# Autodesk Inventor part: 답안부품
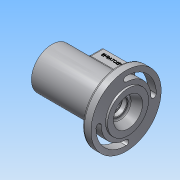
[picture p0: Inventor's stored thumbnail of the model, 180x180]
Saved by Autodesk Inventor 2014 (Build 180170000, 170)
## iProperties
Created: 2017-05
Part Number: 답안부품
Material: 알루미늄 6061
Document SubType Name: Modeling
Designer: NET
Density: 2.71 g/cm^3
Appearance: 알루미늄 - 평지
Mass: 734.189 g
Surface Area: 637.35 cm^2
Volume: 270.918 cm^3
Author: NET
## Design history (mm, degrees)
sketch "스케치1"
  geometry: L1 (-57.5, 31)-(57.5, 31); L2 (57.5, 31)-(57.5, 0); L3 (57.5, 0)-(-57.5, 0); L4 (-57.5, 0)-(-57.5, 31); 2 further points
  constraints: 8 end point, 2 coincident, 2 parallel, 1 horizontal, 1 midpoint, 1 perpendicular
  dimensions: "d0" = 62 diameter of L1.end L3; "d1" = 115 distance of L1.start L1.end
revolve "회전1" sketch "스케치1" stored, may be unused: angle "d2" = 90 deg
node "작업 평면1"
sketch "스케치2"
  geometry: C1 r 53 at (0, 0); 1 further point
  constraints: 1 centre point, 1 coincident
  dimensions: "d4" = 106 diameter of C1
extrude "돌출1" join sketch "스케치2" distance "d5" = 13; taper "d6" = 0 deg
fillet "모깎기1" dims "d7" = 3
sketch "스케치3"
  geometry: L1 (-57.5, -31)-(-57.5, 31) reference; L2 (-57.5, 31)-(41.5, 31) reference; L3 (41.5, 31)-(41.5, 50) reference; L4 (44.5, 53)-(54.5, 53) reference; L5 (54.5, 53)-(54.5, 31) reference; L6 (54.5, 31)-(57.5, 31) reference; L7 (57.5, 31)-(57.5, -31) reference; L8 (57.5, -31)-(54.5, -31) reference; L9 (54.5, -31)-(54.5, -53) reference; L10 (54.5, -53)-(44.5, -53) reference; L11 (41.5, -50)-(41.5, -31) reference; L12 (41.5, -31)-(-57.5, -31) reference; L13 (-57.5, 0)-(57.5, 0); L14 (57.5, 0)-(57.5, 22); L15 (57.5, 22)-(45.318, 16.779); L16 (43.5, 14.022)-(43.5, 12.904); L17 (42.8, 12.5)-(36.5, 12.5); L18 (36.2, 12.2)-(36.2, 10); L19 (36.2, 10)-(33.5, 10); L20 (33.5, 10)-(33.5, 13.5); L21 (30.5, 16.5)-(28.5, 16.5); L22 (28.5, 16.5)-(28.5, 17.2); L23 (28.2, 17.5)-(18.5, 17.5); L24 (17.5, 18.5)-(17.5, 23); L25 (43.5, 12.904)-(42.8, 12.5); L26 (14.5, 26)-(-17.5, 26); L27 (-20.5, 23)-(-20.5, 18.5); L28 (-21.5, 17.5)-(-31.5, 17.5); L29 (-31.5, 17.5)-(-31.5, 18.5); L30 (-31.5, 18.5)-(-33.25, 18.5); L31 (-33.25, 18.5)-(-33.25, 17.5); L32 (-33.25, 17.5)-(-39.5, 17.5); L33 (-39.5, 17.5)-(-39.5, 20); L34 (-39.5, 20)-(-45.5, 20); L35 (-45.5, 20)-(-45.5, 24); L36 (-45.5, 24)-(-48.5, 24); L37 (-48.5, 24)-(-48.5, 0); L38 (-21.5, 17.5)-(-20.5, 18.5); L39 (17.5, 18.5)-(18.5, 17.5); A1 r 3 centre (44.5, 50) between (44.5, 53) and (41.5, 50) reference; A2 r 3 centre (44.5, -50) between (41.5, -50) and (44.5, -53) reference; A3 r 0.3 centre (36.5, 12.2) between (36.5, 12.5) and (36.2, 12.2); A4 r 3 centre (30.5, 13.5) between (33.5, 13.5) and (30.5, 16.5); A5 r 3 centre (46.5, 14.022) between (45.318, 16.779) and (43.5, 14.022); A6 r 3 centre (14.5, 23) between (17.5, 23) and (14.5, 26); A7 r 3 centre (-17.5, 23) between (-17.5, 26) and (-20.5, 23); A8 r 0.3 centre (28.2, 17.2) between (28.5, 17.2) and (28.2, 17.5); 11 further points
  constraints: 54 end point, 18 point on line, 13 perpendicular, 12 point on circle, 12 tangent, 7 parallel, 6 centre point, 3 midpoint, 1 collinear, 1 vertical alignment
  dimensions: "d57" = 24 horizontal distance of L13.end point (33.5, 16.5); "d58" = 5 distance of point (33.5, 16.5) L21.end; "d62" = 44 diameter of L14.end L13; "d64" = 14 distance from line of L14.end L16; "d66" = 32 diameter of point (43.5, 16) L13; "d67" = 30 deg angle of L25 L17; "d68" = 0.7 horizontal distance of L16.end L17.start; "d69" = 7.3 horizontal distance of L16.end point (36.2, 12.5); "d70" = 0.3 radius of A3; "d71" = 25 diameter of L17 L13; "d72" = 20 diameter of L19 L13; "d73" = 33 diameter of L21 L13; "d75" = 3 radius of A4; "d76" = 3 radius of A5; "d77" = 11 distance of point (28.5, 17.5) point (17.5, 17.5); "d78" = 38 distance of point (17.5, 26) point (-20.5, 26); "d79" = 52 diameter of L26 L13; "d80" = 35 diameter of L23 L13; "d81" = 3 radius of A6; "d82" = 3 radius of A7; "d83" = 11 distance of point (-20.5, 17.5) L28.end; "d84" = 1.75 distance of L29.end L30.end; "d85" = 35 diameter of L28 L13; "d86" = 1 distance of L28.start point (-20.5, 17.5); "d87" = 1 distance of L27.end point (-20.5, 17.5) (= d86); "d88" = 1 distance of L24.start point (17.5, 17.5) (= d86); "d89" = 1 distance of L23.end point (17.5, 17.5) (= d88); "d90" = 37 diameter of L30 L13; "d91" = 3 distance of L35.end L36.end; "d92" = 9 horizontal distance of L36.end L33.end; "d93" = 17 horizontal distance of L36.end L29.end; "d94" = 48 diameter of L36 L13; "d95" = 40 diameter of L34 L13; "d96" = 35 diameter of L32 L13; "d97" = 0.3 radius of A8
revolve "회전2" sketch "스케치3" stored, may be unused: angle "d98" = 90 deg
sketch "스케치4"
  geometry: C1 r 31 at (0, 0) reference; 1 further point
  constraints: 1 coincident
hole "구멍1" sketch "스케치4" at (0, 0) diameter "d99" = 40.376; stored, may be unused: countersink angle "d103" = 90 deg, drill point angle "d105" = 0 deg; dims "d100" = 9, "d101" = 4, "d102" = 2, "d104" = 11
sketch "스케치5"
  geometry: C1 r 31 at (0, 0) reference; A1 r 41.5 centre (0, 0) between (41.5, 0) and (0, -41.5); A2 r 4 centre (41.5, 0) between (45.5, 0) and (37.5, 0); A3 r 4 centre (0, -41.5) between (0, -37.5) and (0, -45.5); A4 r 4 centre (0, 41.5) between (0, 37.5) and (0, 45.5); A5 r 4 centre (-41.5, 0) between (-45.5, 0) and (-37.5, 0); A6 r 45.5 centre (0, 0) between (0, 45.5) and (-45.5, 0); A7 r 45.5 centre (0, 0) between (0, -45.5) and (45.5, 0); A8 r 37.5 centre (0, 0) between (0, 37.5) and (-37.5, 0); A9 r 37.5 centre (0, 0) between (0, -37.5) and (37.5, 0)
  constraints: 20 point on circle, 9 centre point, 3 coincident
  dimensions: "d106" = 83 diameter of A1; "d109" = 8 diameter of A2; "d110" = 8 diameter of A3; "d111" = 8 diameter of A4; "d112" = 8 diameter of A5
extrude "돌출2" cut sketch "스케치5" stored distance "d113" = 14; taper "d114" = 0 deg
node "작업 평면2"
sketch "스케치6"
  geometry: L1 (-23.5, -20)-(-23.5, 20); L2 (-23.5, 20)-(26.5, 20); L3 (26.5, 20)-(26.5, -20); L4 (26.5, -20)-(-23.5, -20); L5 (1.5, -20)-(1.5, 20); L6 (-23.5, 0)-(26.5, 0); L7 (57.5, 31)-(57.5, -31) reference; 1 further point
  constraints: 12 end point, 4 midpoint, 2 parallel, 2 perpendicular, 1 horizontal alignment, 1 vertical
  dimensions: "d118" = 56 distance from line of L5.start L7; "d119" = 50 distance from line of L1 L6.end; "d120" = 40 distance between parallel lines of L2 L4
extrude "돌출3" join sketch "스케치6" stored distance "d121" = 14; taper "d122" = 0 deg
sketch "스케치7"
  geometry: L1 (-26.5, 20)-(23.5, 20) reference; L2 (-26.5, -20)-(-26.5, 20) reference; L3 (23.5, -20)-(-26.5, -20) reference; L4 (-1.5, 20)-(-1.5, -20); L5 (-17.5, 11)-(14.5, 11); L6 (14.5, 11)-(14.5, -11); L7 (14.5, -11)-(-17.5, -11); L8 (-17.5, -11)-(-17.5, 11); 4 further points
  constraints: 10 end point, 5 midpoint, 2 parallel, 1 horizontal, 1 horizontal alignment, 1 perpendicular, 1 vertical alignment
  dimensions: "d129" = 32 distance of L5.start L5.end; "d130" = 22 distance of L5.end L6.end
extrude "돌출4" cut sketch "스케치7" stored distance "d125" = 14; taper "d126" = 0 deg
fillet "모깎기2" dims "d127" = 3
fillet "모깎기3" dims "d128" = 3
sketch "스케치8"
  geometry: L1 (-17.5, 11)-(14.5, 11) reference; L2 (14.5, -11)-(-17.5, -11) reference; L3 (-1.5, 11)-(-1.5, -11); L4 (-22, 15.5)-(19, 15.5); L5 (19, 15.5)-(19, -15.5); L6 (19, -15.5)-(-22, -15.5); L7 (-22, -15.5)-(-22, 15.5); 9 further points
  constraints: 10 end point, 6 midpoint, 4 coincident, 2 parallel, 1 horizontal, 1 horizontal alignment, 1 perpendicular, 1 vertical alignment
  dimensions: "d132" = 41 distance of L4.start L4.end; "d133" = 31 distance of L4.end L5.end
hole "구멍2" sketch "스케치8" at (-22, 15.5), (19, 15.5), (-22, -15.5), (19, -15.5) diameter "d134" = 2.459; stored, may be unused: countersink angle "d138" = 90 deg, drill point angle "d140" = 118 deg; dims "d135" = 6, "d136" = 4, "d137" = 2, "d139" = 8
fillet "모깎기4" dims "d141" = 3
chamfer "모따기1" distance "d142" = 1; stored, may be unused: second distance "d143" = 2, angle "d144" = 45 deg
sketch "스케치9"
  geometry: L1 (44, 0)-(0, 0) reference; L2 (-34, -75)-(-34, -13) reference; 2 further points
  constraints: 1 other
  dimensions: "d145" = 56 distance from line of point (22, -8) L2; "d146" = 8 distance from line of L1 point (22, -8)
feature "엠보싱1" sketch "스케치9" dims "d147" = 0.5, "d148" = 0
chamfer "모따기2" distance "d149" = 1; stored, may be unused: second distance "d150" = 2, angle "d151" = 45 deg
node "솔리드1"
node "절단 모서리 투영1"
other parameters: "d3" = -3, "d107" = 75, "d108" = 91, "d115" = 44
